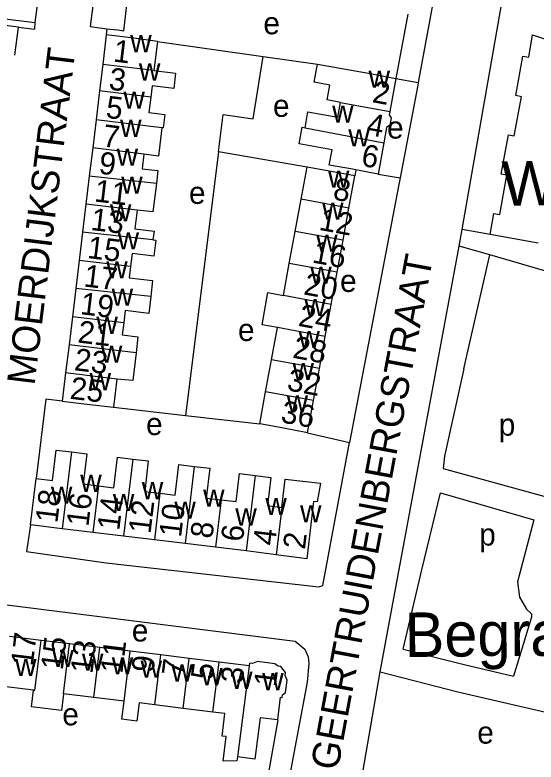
# Model space of a CAD drawing. Extents: x 157569 to 159501, y 382907 to 384670.
# Drawn here: x 158503.7 to 158597.5, y 383217.2 to 383351.5 of the extents above; entities that cross this region are included whole.
import ezdxf

# ---------------------------------------------------------------- set-up
doc = ezdxf.new("R2010")
doc.units = 0
for name, color, linetype in [('BLT_Basislijn', 7, 'Continuous'), ('BLT_Bebouwing', 7, 'Continuous'), ('BLT_Bebouwing_beschrifting', 7, 'Continuous'), ('BLT_Centroide', 7, 'Continuous'), ('BLT_Huisnummer', 7, 'Continuous'), ('BLT_Huisnummer_ tussenligend', 7, 'Continuous'), ('BLT_Onderverdeling_panden', 7, 'Continuous'), ('BLT_Straatnaam', 7, 'Continuous'), ('BLT_Terrein_beschrifting', 7, 'Continuous')]:
    doc.layers.add(name, color=color, linetype=linetype)

msp = doc.modelspace()

# ---------------------------------------------------------------- linework, layer by layer
at = {"layer": 'BLT_Basislijn'}
for p, q in [((158574.38, 383351.71), (158572.21, 383340.14)), ((158504.28, 383349.36), (158507.16, 383348.97)), ((158520.23, 383349.08), (158520.11, 383347.97)), ((158529.32, 383346.78), (158548.32, 383344.09)), ((158546.54, 383332.87), (158548.32, 383344.09)), ((158548.32, 383344.09), (158558.13, 383342.71)), ((158572.21, 383340.14), (158576.25, 383339.41)), ((158540.32, 383326.94), (158534.38, 383279.52)), ((158556.23, 383324.17), (158540.32, 383326.94)), ((158565.04, 383323.67), (158564.84, 383322.59)), ((158569.01, 383322.94), (158573.01, 383322.25)), ((158583.63, 383309.99), (158584.16, 383312.97)), ((158589.18, 383312.06), (158584.16, 383312.97)), ((158569.38, 383233.38), (158583.63, 383309.99)), ((158589.14, 383308.43), (158583.63, 383309.99)), ((158584.44, 383287.9), (158589.14, 383308.43)), ((158606.67, 383303.22), (158589.14, 383308.43)), ((158521.41, 383280.99), (158534.38, 383279.52)), ((158534.38, 383279.52), (158547.72, 383278.01)), ((158556.33, 383276.42), (158563.9, 383274.65)), ((158564.62, 383205.89), (158569.38, 383233.38)), ((158550.98, 383224.75), (158549.26, 383214.95))]:
    msp.add_line(p, q, dxfattribs=at)
for points in [[(158581.08, 383365.73), (158576.25, 383339.41)], [(158584.16, 383312.97), (158584.47, 383314.69), (158591.88, 383357.2), (158592.52, 383359.69), (158594.44, 383361.47), (158597.79, 383361.19), (158631.42, 383350.05), (158632.2, 383349.79)], [(158576.25, 383339.41), (158576.16, 383338.92), (158573.01, 383322.25)], [(158540.32, 383326.94), (158541.15, 383333.63), (158546.54, 383332.87)], [(158573.01, 383322.25), (158572.78, 383321.06), (158563.9, 383274.65)], [(158584.44, 383287.9), (158580.99, 383272.2), (158580.74, 383269.99), (158599.91, 383264.7), (158600.51, 383264.82), (158605.03, 383282.14)], [(158512.18, 383282.1), (158509.23, 383282.44), (158507.48, 383268.19)], [(158558.38, 383248.67), (158559.09, 383248.96), (158563.9, 383274.65)], [(158576.9, 383251.77), (158580.23, 383265.6), (158597.06, 383260.74)], [(158597.06, 383260.74), (158594.09, 383249.59), (158594.44, 383246.86), (158595.72, 383244.7), (158596.64, 383243.85), (158596.62, 383243.26), (158593.41, 383232.63)], [(158506.47, 383259.84), (158505.74, 383255.02), (158520.08, 383253), (158558.38, 383248.67)], [(158573.53, 383237.48), (158576.9, 383251.77)], [(158496.96, 383246.09), (158554.1, 383238.91), (158555.85, 383237.47)], [(158555.85, 383237.47), (158556.46, 383236.09), (158556.55, 383234.91), (158556.23, 383231.55), (158545.62, 383175.03)], [(158573.53, 383237.48), (158584.53, 383234.7), (158593.41, 383232.63)], [(158569.38, 383233.38), (158583.35, 383229.84), (158615.03, 383222.48)]]:
    msp.add_lwpolyline(points, dxfattribs=at)
at = {"layer": 'BLT_Bebouwing'}
for p, q in [((158508.17, 383357.48), (158507.27, 383350.18)), ((158503.65, 383344.29), (158504.28, 383349.36)), ((158507.27, 383350.18), (158507.16, 383348.97)), ((158520.11, 383347.97), (158519.46, 383342.64)), ((158529.32, 383346.78), (158528.69, 383341.53)), ((158519.46, 383342.64), (158518.89, 383337.89)), ((158572.21, 383340.14), (158571.11, 383334.19)), ((158518.89, 383337.89), (158518.27, 383332.71)), ((158518.27, 383332.71), (158517.66, 383327.64)), ((158517.66, 383327.64), (158517.05, 383322.58)), ((158570.04, 383328.54), (158569.01, 383322.94)), ((158555.17, 383318.41), (158556.23, 383324.17)), ((158569.01, 383322.94), (158565.04, 383323.67)), ((158517.05, 383322.58), (158516.44, 383317.52)), ((158563.78, 383316.82), (158564.84, 383322.59)), ((158554.1, 383312.63), (158555.17, 383318.41)), ((158516.44, 383317.52), (158515.84, 383312.46)), ((158562.71, 383311.05), (158563.78, 383316.82)), ((158515.84, 383312.46), (158515.23, 383307.4)), ((158553.04, 383306.86), (158554.1, 383312.63)), ((158597.83, 383310.49), (158589.18, 383312.06)), ((158561.65, 383305.28), (158562.71, 383311.05)), ((158515.23, 383307.4), (158514.62, 383302.34)), ((158551.97, 383301.09), (158553.04, 383306.86)), ((158560.59, 383299.5), (158561.65, 383305.28)), ((158514.62, 383302.34), (158514.01, 383297.28)), ((158559.52, 383293.73), (158560.59, 383299.5)), ((158514.01, 383297.28), (158513.4, 383292.22)), ((158549.85, 383289.55), (158550.91, 383295.32)), ((158558.46, 383287.96), (158559.52, 383293.73)), ((158513.4, 383292.22), (158512.79, 383287.16)), ((158548.78, 383283.78), (158549.85, 383289.55)), ((158557.4, 383282.19), (158558.46, 383287.96)), ((158512.79, 383287.16), (158512.18, 383282.1)), ((158522.02, 383286.05), (158521.41, 383280.99)), ((158547.72, 383278.01), (158548.78, 383283.78)), ((158556.33, 383276.42), (158557.4, 383282.19)), ((158506.47, 383259.84), (158507.48, 383268.19)), ((158512.16, 383259.15), (158506.47, 383259.84)), ((158517.69, 383258.49), (158512.16, 383259.15)), ((158523.23, 383257.82), (158517.69, 383258.49)), ((158528.76, 383257.15), (158523.23, 383257.82)), ((158534.28, 383256.49), (158528.76, 383257.15)), ((158539.76, 383255.83), (158534.28, 383256.49)), ((158545.26, 383255.17), (158539.76, 383255.83)), ((158550.67, 383254.43), (158545.26, 383255.17)), ((158508.37, 383239.07), (158502.71, 383239.76)), ((158513.5, 383238.45), (158508.37, 383239.07)), ((158518.96, 383237.78), (158513.5, 383238.45)), ((158524.4, 383237.12), (158518.96, 383237.78)), ((158529.9, 383236.44), (158524.4, 383237.12)), ((158535.05, 383235.82), (158529.9, 383236.44)), ((158540.41, 383235.16), (158535.05, 383235.82)), ((158545.79, 383234.51), (158540.41, 383235.16)), ((158507.02, 383230.14), (158501.62, 383230.8)), ((158517.86, 383228.81), (158512.42, 383229.48)), ((158523.32, 383228.14), (158517.86, 383228.81)), ((158533.95, 383226.84), (158528.82, 383227.47)), ((158539.31, 383226.18), (158533.95, 383226.84))]:
    msp.add_line(p, q, dxfattribs=at)
for points in [[(158519.73, 383369.12), (158517.21, 383349.45), (158520.23, 383349.08)], [(158501.74, 383357.68), (158500.92, 383350.96), (158507.27, 383350.18)], [(158520.23, 383349.08), (158522.18, 383348.85), (158523.24, 383348.72), (158523.73, 383352.83), (158524.43, 383358.19)], [(158504.28, 383349.36), (158500, 383349.89), (158499.32, 383349.98), (158495.08, 383350.46)], [(158589.18, 383312.06), (158589.87, 383315.84), (158590.92, 383315.65), (158592.19, 383322.71), (158591.17, 383322.9), (158592.48, 383330), (158593.52, 383329.8), (158594.82, 383336.85), (158593.78, 383337.05), (158595.09, 383344.14), (158596.12, 383343.93), (158596.79, 383347.97), (158599.48, 383347.07), (158600.48, 383349.74), (158601.87, 383349.3), (158602.74, 383349.78), (158603.24, 383351.22)], [(158529.32, 383346.78), (158525.07, 383347.37), (158520.11, 383347.97)], [(158562.25, 383335.82), (158559.83, 383336.27), (158560.32, 383338.94), (158557.53, 383339.45), (158558.13, 383342.71)], [(158558.13, 383342.71), (158563.9, 383341.65), (158567.29, 383341.05), (158572.21, 383340.14)], [(158528.69, 383341.53), (158532.59, 383341.06), (158532.26, 383338.34), (158528.37, 383338.81), (158528.12, 383336.78)], [(158528.12, 383336.78), (158527.78, 383333.98), (158530.62, 383333.64), (158530.33, 383331.25), (158530.12, 383331.27)], [(158555.87, 383331.25), (158556.4, 383334.14), (158561.76, 383333.16), (158562.25, 383335.82)], [(158571.11, 383334.19), (158571.01, 383333.61), (158571.38, 383333.06), (158571.14, 383331.72), (158570.55, 383331.31), (158570.04, 383328.54)], [(158530.12, 383331.27), (158529.51, 383326.17), (158526.89, 383326.53)], [(158554.79, 383328.38), (158555.34, 383331.35), (158555.87, 383331.25)], [(158565.04, 383323.67), (158564.09, 383323.85), (158560.24, 383324.56), (158560.74, 383327.29), (158554.79, 383328.38), (158554.79, 383328.38)], [(158526.89, 383326.53), (158526.57, 383323.89), (158529.4, 383323.55), (158529.12, 383321.23)], [(158564.84, 383322.59), (158559.92, 383323.49), (158556.23, 383324.17)], [(158529.12, 383321.23), (158528.51, 383316.16), (158525.67, 383316.41)], [(158525.67, 383316.41), (158525.27, 383313.07), (158528.7, 383312.66), (158528.51, 383311.1)], [(158528.51, 383311.1), (158529.02, 383311.04), (158528.68, 383308.16), (158524.74, 383308.63), (158524.46, 383306.29)], [(158524.46, 383306.29), (158524.21, 383304.29), (158528.45, 383303.78), (158528.1, 383300.91)], [(158528.1, 383300.91), (158527.74, 383297.87), (158523.5, 383298.38), (158523.24, 383296.17)], [(158550.91, 383295.32), (158548.14, 383295.84), (158549.2, 383301.62), (158551.97, 383301.09)], [(158523.24, 383296.17), (158522.98, 383294), (158525.81, 383293.66), (158525.46, 383290.77)], [(158525.46, 383290.77), (158524.86, 383285.8), (158522.02, 383286.05)], [(158512.18, 383282.1), (158517.15, 383281.5), (158521.41, 383280.99)], [(158556.33, 383276.42), (158551.42, 383277.33), (158547.72, 383278.01)], [(158507.48, 383268.19), (158510.4, 383267.84), (158511.06, 383273.3), (158513.82, 383272.97)], [(158513.82, 383272.97), (158516.59, 383272.64), (158515.93, 383267.2), (158518.7, 383266.86)], [(158518.7, 383266.86), (158521.46, 383266.53), (158522.12, 383272), (158524.89, 383271.67)], [(158524.89, 383271.67), (158527.66, 383271.34), (158527.04, 383265.86), (158529.77, 383265.53)], [(158529.77, 383265.53), (158532.51, 383265.2), (158533.17, 383270.67), (158535.95, 383270.34)], [(158535.95, 383270.34), (158538.73, 383270.01), (158538.09, 383264.67), (158540.78, 383264.35)], [(158540.78, 383264.35), (158543.48, 383264.02), (158544.09, 383269.05), (158546.89, 383268.72)], [(158546.89, 383268.72), (158549.7, 383268.38), (158549.09, 383263.35), (158551.7, 383262.95)], [(158551.7, 383262.95), (158552.31, 383268.04), (158558.68, 383267.33), (158558.08, 383263.98), (158557.37, 383264.07), (158556.18, 383253.75), (158550.67, 383254.43)], [(158550.98, 383224.75), (158551.48, 383228.84), (158551.75, 383228.81), (158551.81, 383229.25), (158552.37, 383229.69), (158552.64, 383231.89), (158552.27, 383232.76), (158552.34, 383233.31), (158551.54, 383234.34), (158551.02, 383234.4), (158550.41, 383234.87), (158547.29, 383235.25), (158546.43, 383234.88), (158545.85, 383234.95), (158545.79, 383234.51)], [(158512.42, 383229.48), (158512.05, 383226.47), (158506.65, 383227.13), (158507.02, 383230.14)], [(158528.82, 383227.47), (158526.01, 383227.81), (158525.61, 383224.55), (158522.93, 383224.88), (158523.32, 383228.14)], [(158543.73, 383218.12), (158543.62, 383217.43), (158541.14, 383217.36), (158541.68, 383221.78), (158540.97, 383221.86), (158541.46, 383225.92), (158539.31, 383226.18)], [(158550.98, 383224.75), (158547.81, 383225.14), (158546.85, 383217.72), (158543.73, 383218.12)]]:
    msp.add_lwpolyline(points, dxfattribs=at)
at = {"layer": 'BLT_Onderverdeling_panden'}
for p, q in [((158528.69, 383341.53), (158519.46, 383342.64)), ((158528.12, 383336.78), (158518.89, 383337.89)), ((158562.25, 383335.82), (158571.11, 383334.19)), ((158530.12, 383331.27), (158518.27, 383332.71)), ((158526.89, 383326.53), (158517.66, 383327.64)), ((158529.12, 383321.23), (158517.05, 383322.58)), ((158563.78, 383316.82), (158555.17, 383318.41)), ((158525.67, 383316.41), (158516.44, 383317.52)), ((158528.51, 383311.1), (158515.84, 383312.46)), ((158562.71, 383311.05), (158554.1, 383312.63)), ((158524.46, 383306.29), (158515.23, 383307.4)), ((158561.65, 383305.28), (158553.04, 383306.86)), ((158528.1, 383300.91), (158514.62, 383302.34)), ((158560.59, 383299.5), (158551.97, 383301.09)), ((158523.24, 383296.17), (158514.01, 383297.28)), ((158559.52, 383293.73), (158550.91, 383295.32)), ((158525.46, 383290.77), (158513.4, 383292.22)), ((158558.46, 383287.96), (158549.85, 383289.55)), ((158522.02, 383286.05), (158512.79, 383287.16)), ((158557.4, 383282.19), (158548.78, 383283.78)), ((158513.82, 383272.97), (158512.16, 383259.15)), ((158524.89, 383271.67), (158523.23, 383257.82)), ((158535.95, 383270.34), (158534.28, 383256.49)), ((158546.89, 383268.72), (158545.26, 383255.17)), ((158518.7, 383266.86), (158517.69, 383258.49)), ((158529.77, 383265.53), (158528.76, 383257.15)), ((158540.78, 383264.35), (158539.76, 383255.83)), ((158551.7, 383262.95), (158550.67, 383254.43)), ((158512.42, 383229.48), (158513.5, 383238.45)), ((158517.86, 383228.81), (158518.96, 383237.78)), ((158523.32, 383228.14), (158524.4, 383237.12)), ((158528.82, 383227.47), (158529.9, 383236.44)), ((158533.95, 383226.84), (158535.05, 383235.82)), ((158539.31, 383226.18), (158540.41, 383235.16)), ((158545.79, 383234.51), (158543.73, 383218.12))]:
    msp.add_line(p, q, dxfattribs=at)
for points in [[(158555.87, 383331.25), (158555.87, 383331.25), (158570.04, 383328.54)], [(158507.02, 383230.14), (158507.27, 383230.11), (158508.37, 383239.07)]]:
    msp.add_lwpolyline(points, dxfattribs=at)

# ---------------------------------------------------------------- texts
at = {"layer": 'BLT_Bebouwing_beschrifting'}
msp.add_text('Woonzorgcentrum', height=8, rotation=0.5505, dxfattribs=at).set_placement((158591.27, 383317.24))
at = {"layer": 'BLT_Centroide'}
for s, p in [('e', (158548.38, 383348.07)), ('w', (158524.41, 383344.84)), ('w', (158525.98, 383339.75)), ('w', (158567.31, 383338.44)), ('w', (158523.19, 383334.69)), ('e', (158550.11, 383333.22)), ('w', (158560.75, 383332.19)), ('w', (158522.59, 383329.62)), ('e', (158570.64, 383329.31)), ('w', (158563.66, 383327.91)), ('w', (158521.96, 383324.44)), ('w', (158560, 383320.5)), ('w', (158522.79, 383319.38)), ('e', (158534.99, 383317.57)), ('w', (158520.76, 383314.44)), ('w', (158558.94, 383314.72)), ('w', (158522.15, 383309.38)), ('w', (158557.88, 383308.97)), ('w', (158520.09, 383304.16)), ('w', (158556.81, 383303.19)), ('e', (158562.18, 383301.73)), ('w', (158521.08, 383299.25)), ('w', (158555.75, 383297.41)), ('w', (158518.32, 383294.19)), ('e', (158543.81, 383292.91)), ('w', (158554.69, 383291.66)), ('w', (158519.13, 383289)), ('w', (158553.62, 383285.88)), ('w', (158517.1, 383284.06)), ('w', (158552.56, 383280.09)), ('e', (158527.27, 383275.99)), ('p', (158590.74, 383275.88)), ('w', (158515.42, 383265.77)), ('w', (158526.5, 383264.45)), ('w', (158510.14, 383263.64)), ('w', (158537.53, 383263.12)), ('w', (158521.3, 383262.31)), ('w', (158548.73, 383261.62)), ('w', (158532.36, 383260.97)), ('w', (158554.98, 383260.31)), ('w', (158543.33, 383259.72)), ('p', (158587.22, 383256.12)), ('e', (158524.7, 383238.86)), ('w', (158510.38, 383234.27)), ('w', (158515.73, 383233.61)), ('w', (158503.69, 383232.66)), ('w', (158521.09, 383232.97)), ('w', (158526.28, 383232.33)), ('w', (158531.81, 383231.66)), ('w', (158537.17, 383231)), ('w', (158542.55, 383230.34)), ('w', (158548.17, 383230.11)), ('e', (158512.2, 383223.78)), ('e', (158586.87, 383220.49))]:
    msp.add_text(s, height=4, dxfattribs=at).set_placement(p)
at = {"layer": 'BLT_Huisnummer'}
for s, rotation, p in [('1', 353.144, (158521.23, 383343.18)), ('2', 349.5592, (158567.82, 383335.88)), ('5', 353.144, (158519.89, 383333.07)), ('6', 349.5599, (158565.82, 383324.46)), ('9', 353.144, (158518.63, 383323.02)), ('8', 349.5571, (158560.74, 383318.4)), ('13', 353.144, (158517.18, 383312.89)), ('16', 349.5559, (158557.01, 383307.05)), ('17', 353.144, (158515.92, 383302.73)), ('24', 349.5612, (158554.51, 383295.65)), ('21', 353.144, (158514.84, 383292.65)), ('25', 353.144, (158513.44, 383282.53)), ('36', 349.5599, (158551.35, 383278.31)), ('18', 83.1293, (158511.3, 383260.04)), ('14', 83.1293, (158522.44, 383258.73)), ('10', 83.1293, (158533.56, 383257.49)), ('6', 83.1293, (158544.68, 383256.68)), ('2', 83.1293, (158555.85, 383255.31)), ('13', 83.0285, (158517.61, 383232.96)), ('9', 83.0285, (158528.59, 383233.16)), ('5', 83.0285, (158539.26, 383231.84)), ('1', 83.0285, (158550.62, 383230.6))]:
    msp.add_text(s, height=4, rotation=rotation, dxfattribs=at).set_placement(p)
at = {"layer": 'BLT_Huisnummer_ tussenligend'}
for s, rotation, p in [('3', 353.144, (158520.44, 383338.14)), ('4', 349.5592, (158566.78, 383330.04)), ('7', 353.144, (158519.3, 383327.92)), ('11', 353.144, (158517.82, 383318.02)), ('12', 349.5571, (158558.23, 383312.92)), ('15', 353.144, (158516.56, 383307.84)), ('20', 349.5559, (158555.47, 383301.31)), ('19', 353.144, (158515.3, 383297.74)), ('28', 349.5612, (158553.49, 383289.92)), ('23', 353.144, (158514.22, 383287.66)), ('32', 349.5612, (158552.46, 383284.07)), ('16', 83.1293, (158516.88, 383259.42)), ('12', 83.1293, (158528.06, 383258.14)), ('8', 83.1293, (158539.18, 383257.26)), ('4', 83.1293, (158550.46, 383255.99)), ('17', 83.0285, (158506.87, 383234.32)), ('15', 83.0285, (158512.27, 383233.59)), ('11', 83.0285, (158522.99, 383232.98)), ('7', 83.0285, (158534.03, 383232.52)), ('3', 83.0285, (158544.65, 383231.19))]:
    msp.add_text(s, height=4, rotation=rotation, dxfattribs=at).set_placement(p)
at = {"layer": 'BLT_Straatnaam'}
for s, height, rotation, p in [('MOERDIJKSTRAAT', 5, 83.0293, (158507.19, 383284.82)), ('GEERTRUIDENBERGSTRAAT', 4.9999, 79.4813, (158561.76, 383215.51))]:
    msp.add_text(s, height=height, rotation=rotation, dxfattribs=at).set_placement(p)
at = {"layer": 'BLT_Terrein_beschrifting'}
msp.add_text('Begraafplaats', height=8, rotation=0.5505, dxfattribs=at).set_placement((158573.84, 383236.06))

doc.saveas('drawing.dxf')
